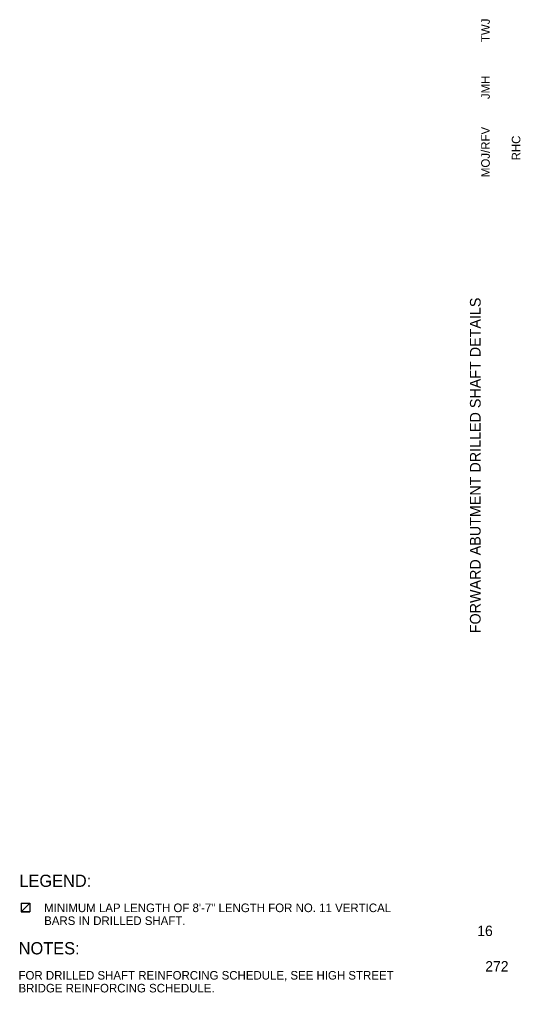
# Model space of a CAD drawing. Extents: x 25.2 to 33.4, y 0.7 to 16.6.
import ezdxf

# ---------------------------------------------------------------- set-up
doc = ezdxf.new("R2010")
doc.units = 0
for name, color, linetype in [('BR_P_Gen_Text', 7, 'Continuous'), ('SH_Data', 7, 'Continuous'), ('SH_Text', 7, 'Continuous')]:
    doc.layers.add(name, color=color, linetype=linetype)

msp = doc.modelspace()

# ---------------------------------------------------------------- linework, layer by layer
at = {"layer": 'BR_P_Gen_Text'}
for p, q in [((25.25, 2.203), (25.389, 2.203)), ((25.25, 2.063), (25.389, 2.203)), ((25.25, 2.203), (25.25, 2.063)), ((25.389, 2.203), (25.389, 2.063)), ((25.25, 2.063), (25.389, 2.063))]:
    msp.add_line(p, q, dxfattribs=at)
msp.add_lwpolyline([(25.25, 2.063), (25.389, 2.203), (25.389, 2.063)], close=True, dxfattribs=at)

# ---------------------------------------------------------------- texts
for s, height, p in [('LEGEND:', 0.2, (25.219, 2.468)), ('MINIMUM LAP LENGTH OF 8\'-7" LENGTH FOR NO. 11 VERTICAL ', 0.14, (25.624, 2.056)), ('BARS IN DRILLED SHAFT.', 0.14, (25.624, 1.846)), ('NOTES:', 0.2, (25.208, 1.365)), ('FOR DRILLED SHAFT REINFORCING SCHEDULE, SEE HIGH STREET ', 0.14, (25.205, 0.953)), ('BRIDGE REINFORCING SCHEDULE.', 0.14, (25.205, 0.743))]:
    msp.add_text(s, height=height, dxfattribs=at).set_placement(p)
at = {"layer": 'SH_Data'}
for s, height, p in [('TWJ', 0.14, (32.903, 16.278)), ('JMH', 0.14, (32.903, 15.346)), ('MOJ/RFV', 0.14, (32.903, 14.071)), ('RHC', 0.14, (33.403, 14.344)), ('FORWARD ABUTMENT DRILLED SHAFT DETAILS', 0.175, (32.754, 6.615))]:
    msp.add_text(s, height=height, rotation=90, dxfattribs=at).set_placement(p)
at = {"layer": 'SH_Text'}
for s, p in [('16', (32.699, 1.665)), ('272', (32.83, 1.085))]:
    msp.add_text(s, height=0.17, dxfattribs=at).set_placement(p)

doc.saveas('drawing.dxf')
